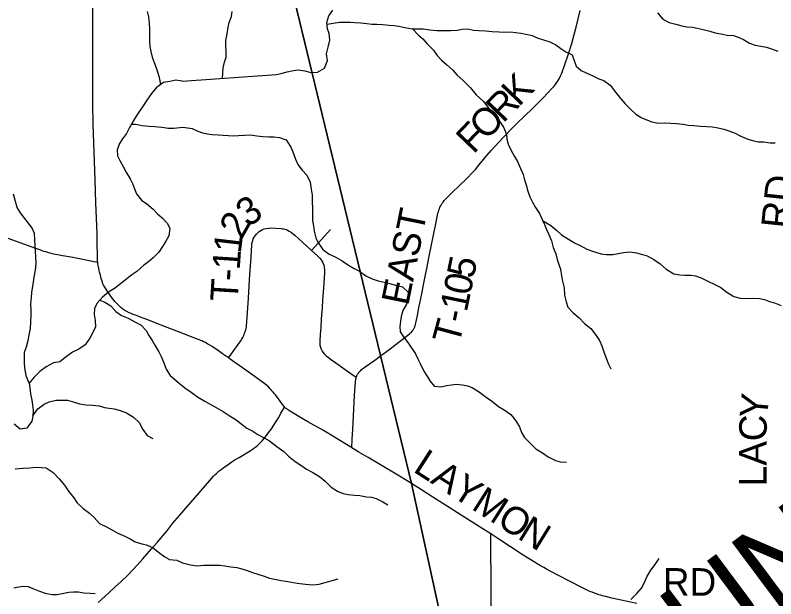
# Model space of a CAD drawing. Extents: x 0 to 48.6, y 0 to 22.
# Drawn here: x 5.524 to 7.09, y 18.416 to 19.616 of the extents above; entities that cross this region are included whole.
import ezdxf

# ---------------------------------------------------------------- set-up
doc = ezdxf.new("R2010")
doc.units = 0
for name, color, linetype in [('GM_X_Corporation', 7, 'Continuous'), ('GM_X_County_Text', 7, 'Continuous'), ('GM_X_Major_River', 7, 'Continuous'), ('GM_X_Minor_River', 7, 'Continuous'), ('GM_X_Township_Road', 7, 'Continuous'), ('GM_X_Township_Road_Text', 7, 'Continuous')]:
    doc.layers.add(name, color=color, linetype=linetype)

msp = doc.modelspace()

# ---------------------------------------------------------------- linework, layer by layer
at = {"layer": 'GM_X_Corporation'}
msp.add_lwpolyline([(5.5264, 17.0064), (5.8387, 17.2541), (6.5365, 17.7727), (6.4996, 17.9212), (6.3396, 18.6531), (6.2759, 18.9159), (6.0412, 19.8859), (5.8236, 20.7829), (5.795, 20.9), (2.1, 20.9), (2.1, 14.1)], dxfattribs=at)
msp.add_lwpolyline([(8.9, 19.5692), (8.9, 20.9), (5.795, 20.9), (5.8236, 20.7829), (6.0412, 19.8859), (6.2759, 18.9159), (6.3396, 18.6531), (6.4996, 17.9212), (6.5365, 17.7727), (6.9471, 18.0777), (7.2261, 18.2847), (8.5348, 19.2897)], close=True, dxfattribs=at)
at = {"layer": 'GM_X_Major_River'}
for points in [[(5.8677, 19.4807), (6.0615, 19.494), (6.071, 19.4961), (6.0835, 19.4998), (6.0965, 19.5026), (6.1067, 19.5036), (6.1203, 19.5019), (6.1328, 19.4987), (6.1461, 19.4993), (6.1606, 19.5071), (6.1665, 19.523), (6.1644, 19.5367), (6.168, 19.5506), (6.1716, 19.565), (6.1699, 19.5783), (6.167, 19.5882), (6.1656, 19.6011), (6.1696, 19.6147), (6.1777, 19.6268)], [(5.8677, 19.4807), (5.8548, 19.4825), (5.8422, 19.4801), (5.8289, 19.4777), (5.8143, 19.467), (5.8045, 19.455), (5.7951, 19.4412), (5.7869, 19.4296), (5.7799, 19.4187), (5.7728, 19.4086), (5.7665, 19.3981), (5.7586, 19.3839), (5.7527, 19.373), (5.7449, 19.3621), (5.7386, 19.3524), (5.7334, 19.3392), (5.7343, 19.3267), (5.739, 19.3171), (5.7467, 19.3033), (5.7529, 19.2921), (5.7606, 19.2795), (5.7654, 19.2699), (5.7693, 19.2592), (5.7733, 19.2489), (5.784, 19.2357), (5.7945, 19.2283), (5.8075, 19.217), (5.8168, 19.2074), (5.8265, 19.1996), (5.8373, 19.188), (5.8424, 19.1773), (5.8398, 19.1621), (5.8339, 19.1516), (5.8268, 19.1404), (5.8197, 19.1288), (5.8077, 19.1172), (5.7981, 19.1091), (5.7884, 19.1021), (5.7745, 19.0887), (5.7641, 19.0821), (5.7533, 19.0739), (5.7437, 19.0665), (5.7305, 19.0554), (5.7159, 19.0466), (5.7036, 19.0362), (5.6915, 19.0228), (5.6871, 19.0127), (5.6865, 19.0005), (5.6885, 18.988), (5.689, 18.975), (5.6842, 18.9645), (5.6771, 18.9518), (5.6681, 18.9383), (5.6547, 18.9291), (5.6416, 18.9233), (5.6285, 18.9137), (5.6158, 18.9033), (5.6028, 18.9009), (5.5875, 18.8925), (5.5748, 18.8832), (5.5631, 18.8717), (5.5526, 18.859), (5.5536, 18.8495), (5.5552, 18.837), (5.558, 18.8244), (5.5597, 18.8149), (5.5606, 18.8035), (5.5599, 18.7909), (5.5578, 18.7807), (5.548, 18.7669), (5.5343, 18.7649), (5.5213, 18.775)]]:
    msp.add_lwpolyline(points, dxfattribs=at)
at = {"layer": 'GM_X_Minor_River'}
for points in [[(5.8236, 19.4738), (5.821, 19.4881), (5.8163, 19.503), (5.8119, 19.5148), (5.8071, 19.527), (5.8035, 19.5415), (5.8017, 19.5518), (5.8007, 19.5613), (5.8012, 19.5719), (5.8007, 19.5882), (5.8001, 19.5993), (5.7987, 19.6126), (5.7962, 19.624)], [(5.9505, 19.4864), (5.9523, 19.5083), (5.9546, 19.5196), (5.9582, 19.5299), (5.9579, 19.542), (5.9572, 19.5526), (5.9573, 19.564), (5.9601, 19.5777), (5.9625, 19.5917), (5.9641, 19.6015), (5.9691, 19.6133), (5.9704, 19.6239)], [(6.8461, 19.6209), (6.8573, 19.6079), (6.8706, 19.6009), (6.8838, 19.5978), (6.8967, 19.5946), (6.9069, 19.5926), (6.9187, 19.5914), (6.9281, 19.5898), (6.9406, 19.587), (6.9543, 19.5835), (6.9652, 19.5803), (6.9766, 19.5779), (6.9895, 19.5755), (7.0028, 19.5743), (7.0126, 19.5712), (7.0235, 19.5661), (7.0356, 19.5588), (7.0477, 19.5545), (7.0705, 19.5505), (7.0811, 19.547), (7.0939, 19.542)], [(6.166, 19.598), (6.1788, 19.6), (6.1918, 19.6018), (6.2039, 19.602), (6.2134, 19.6019), (6.2229, 19.6015), (6.2354, 19.6006), (6.2479, 19.599), (6.2581, 19.5981), (6.2687, 19.5976), (6.2805, 19.5968), (6.2938, 19.5955), (6.304, 19.595), (6.3135, 19.5934), (6.326, 19.591), (6.3411, 19.5883), (6.3514, 19.5882), (6.3639, 19.5884), (6.3772, 19.5864), (6.3916, 19.5851), (6.4022, 19.5847), (6.4208, 19.5845), (6.4341, 19.5855), (6.4443, 19.5873), (6.4557, 19.588), (6.4675, 19.5856), (6.4785, 19.5847), (6.4921, 19.5838), (6.5058, 19.5826), (6.5202, 19.5817), (6.5304, 19.5812), (6.5437, 19.5819), (6.5536, 19.581), (6.5653, 19.579), (6.5786, 19.5766), (6.5884, 19.5742), (6.5986, 19.57), (6.6119, 19.5657), (6.6247, 19.5614), (6.6372, 19.5552), (6.6474, 19.5479), (6.6575, 19.541), (6.6704, 19.5348), (6.6756, 19.5207), (6.6789, 19.5112), (6.6891, 19.5024), (6.6993, 19.4977), (6.7121, 19.4923), (6.7257, 19.4853), (6.7356, 19.4818), (6.7488, 19.4726), (6.7596, 19.4581), (6.7709, 19.4439), (6.7799, 19.434), (6.7916, 19.4221), (6.8014, 19.4129), (6.8127, 19.4056), (6.8225, 19.4017), (6.8346, 19.397), (6.8482, 19.3943), (6.8604, 19.3949), (6.8737, 19.394), (6.8854, 19.3935), (6.8991, 19.3919), (6.9097, 19.3903), (6.9214, 19.3894), (6.9351, 19.3882), (6.9476, 19.3873), (6.9586, 19.3868), (6.9681, 19.3852), (6.9828, 19.3817), (6.993, 19.3781), (7.0063, 19.3735), (7.018, 19.3677), (7.0324, 19.3611), (7.0445, 19.3576), (7.0543, 19.356), (7.0646, 19.3555), (7.0782, 19.3535), (7.0884, 19.3538)], [(6.3419, 19.5882), (6.3532, 19.5756), (6.3633, 19.5676), (6.372, 19.5572), (6.3848, 19.5446), (6.3926, 19.5335), (6.4017, 19.5239), (6.4126, 19.5144), (6.4239, 19.5036), (6.4329, 19.4937), (6.4464, 19.4818), (6.4611, 19.4665), (6.4731, 19.4527), (6.487, 19.4393), (6.4979, 19.4263), (6.5084, 19.414), (6.5193, 19.4003), (6.5294, 19.3861), (6.5354, 19.3717), (6.5361, 19.361), (6.539, 19.3511), (6.5453, 19.3378), (6.5521, 19.3256), (6.5577, 19.3153), (6.564, 19.3012), (6.5696, 19.2886), (6.5725, 19.2776), (6.5758, 19.2673), (6.5791, 19.254), (6.5836, 19.2426), (6.5892, 19.2319), (6.5951, 19.2204), (6.603, 19.2082), (6.6086, 19.196), (6.6138, 19.1854), (6.6179, 19.1754), (6.6227, 19.1648), (6.6283, 19.1522), (6.6316, 19.1381), (6.6368, 19.1252), (6.6394, 19.1138), (6.6431, 19.1035), (6.6464, 19.0936), (6.6489, 19.0803), (6.6507, 19.0693), (6.654, 19.0556), (6.6546, 19.04), (6.6583, 19.0267), (6.662, 19.0153), (6.6729, 19.0038), (6.6842, 18.9946), (6.6963, 18.9823), (6.7087, 18.9719), (6.7203, 18.957), (6.7267, 18.9467), (6.7315, 18.9361), (6.7356, 18.9235), (6.7404, 18.9105), (6.7456, 18.8983), (6.7504, 18.8888)], [(5.7631, 19.392), (5.7715, 19.392), (5.7852, 19.3895), (5.7988, 19.3878), (5.8113, 19.3873), (5.8254, 19.386), (5.8394, 19.3835), (5.8502, 19.3837), (5.8688, 19.3857)], [(5.8688, 19.3857), (5.8878, 19.3832), (5.8995, 19.3778), (5.9094, 19.3743), (5.9196, 19.3719), (5.929, 19.3707), (5.9419, 19.3702), (5.9518, 19.3697), (5.9632, 19.3689), (5.9742, 19.3684), (5.9837, 19.3687), (5.9962, 19.3697), (6.0091, 19.37), (6.0216, 19.3684), (6.0334, 19.3667), (6.0459, 19.3662), (6.0561, 19.3661), (6.0682, 19.3645), (6.0819, 19.3598), (6.0912, 19.3449), (6.0953, 19.335), (6.1009, 19.3202), (6.1057, 19.3088), (6.1147, 19.2973), (6.1241, 19.2873), (6.1308, 19.2729), (6.1333, 19.2584), (6.1351, 19.2459), (6.1354, 19.233), (6.1356, 19.2185), (6.1359, 19.206), (6.1362, 19.1935), (6.138, 19.1832), (6.1394, 19.1718), (6.1427, 19.1585), (6.1468, 19.149), (6.1569, 19.1345), (6.1701, 19.1249), (6.1826, 19.119), (6.1973, 19.1109), (6.2101, 19.1021), (6.2218, 19.0948), (6.2324, 19.0894), (6.2456, 19.0801), (6.2588, 19.0739), (6.2709, 19.07), (6.2808, 19.0677), (6.2948, 19.0641), (6.3065, 19.061), (6.3213, 19.0571), (6.3329, 19.0463), (6.3351, 19.0364), (6.3293, 19.0217), (6.322, 19.0085), (6.3188, 18.9964), (6.3172, 18.9865), (6.316, 18.9755), (6.3167, 18.9649), (6.3234, 18.9546), (6.3324, 18.9427), (6.3388, 18.9328), (6.3474, 18.9206), (6.353, 18.9095), (6.3578, 18.8996), (6.3649, 18.884), (6.3716, 18.874), (6.3784, 18.863), (6.3866, 18.853), (6.401, 18.8517), (6.4117, 18.8543), (6.4219, 18.8561), (6.4318, 18.8572), (6.4447, 18.8555), (6.4549, 18.8539), (6.4648, 18.85), (6.4795, 18.8408), (6.4938, 18.8304), (6.5047, 18.8227), (6.5187, 18.8112), (6.5308, 18.8043), (6.5443, 18.795), (6.5549, 18.782), (6.5623, 18.7691), (6.566, 18.7576), (6.5724, 18.7477), (6.5844, 18.7358), (6.5961, 18.7243), (6.6097, 18.7159), (6.6213, 18.7074), (6.6361, 18.7004), (6.6459, 18.6977), (6.6588, 18.6968)], [(5.5526, 18.859), (5.5467, 18.8725), (5.5446, 18.8862), (5.5432, 18.8992), (5.543, 18.9094), (5.5432, 18.9227), (5.5467, 18.9337), (5.5503, 18.9469), (5.5527, 18.9583), (5.5552, 18.9715), (5.5561, 18.9852), (5.5567, 18.9988), (5.5564, 19.0095), (5.5562, 19.0216), (5.5572, 19.0353), (5.5581, 19.0455), (5.5606, 19.0626), (5.563, 19.0773), (5.5655, 19.0917), (5.5668, 19.105), (5.5663, 19.1198), (5.5656, 19.1297), (5.565, 19.1411), (5.5644, 19.1551), (5.5638, 19.1669), (5.559, 19.1784), (5.5508, 19.1883), (5.5437, 19.1983), (5.5348, 19.2098), (5.5281, 19.2209), (5.5241, 19.2327), (5.5205, 19.2479)], [(6.6098, 19.1936), (6.6267, 19.1833), (6.6387, 19.173), (6.6489, 19.1645), (6.6629, 19.1557), (6.6753, 19.148), (6.6874, 19.1426), (6.701, 19.1348), (6.7146, 19.1302), (6.7301, 19.1251), (6.7411, 19.1239), (6.7544, 19.1241), (6.7651, 19.1263), (6.7765, 19.1281), (6.7898, 19.1291), (6.8034, 19.1271), (6.8155, 19.1239), (6.8253, 19.1212), (6.8389, 19.1139), (6.8518, 19.1046), (6.8642, 19.0935), (6.8797, 19.0843), (6.8925, 19.0822), (6.9028, 19.0814), (6.9153, 19.0817), (6.9248, 19.0801), (6.9373, 19.075), (6.9497, 19.0688), (6.9645, 19.0622), (6.9765, 19.0557), (6.9894, 19.0461), (7.0037, 19.0372), (7.0166, 19.0341), (7.0272, 19.0336), (7.042, 19.0338), (7.056, 19.0333), (7.0666, 19.0313), (7.0772, 19.0274), (7.0871, 19.0243), (7.101, 19.0192)], [(5.6979, 19.0299), (5.7082, 19.0257), (5.721, 19.0183), (5.7311, 19.0064), (5.7428, 18.9987), (5.7564, 18.9928), (5.77, 18.9854), (5.7832, 18.9784), (5.7933, 18.9677), (5.7992, 18.957), (5.8059, 18.947), (5.8111, 18.9371), (5.8193, 18.9237), (5.8241, 18.9141), (5.8296, 18.9011), (5.8348, 18.8878), (5.843, 18.8752), (5.8617, 18.8589)], [(5.8617, 18.8589), (5.8732, 18.8493), (5.8861, 18.8409), (5.8993, 18.8312), (5.914, 18.8224), (5.9238, 18.8166), (5.9378, 18.8089), (5.9517, 18.8008), (5.9642, 18.7927), (5.9785, 18.7838), (5.9883, 18.7765), (6.0004, 18.7669), (6.0128, 18.7604), (6.0234, 18.7538), (6.0362, 18.7465), (6.0472, 18.7403), (6.0623, 18.7288), (6.0766, 18.7184), (6.0864, 18.7092), (6.1003, 18.6981), (6.1139, 18.6889), (6.1237, 18.6823), (6.1369, 18.6754), (6.1501, 18.6669), (6.1622, 18.6573), (6.1742, 18.6454), (6.1874, 18.637), (6.1991, 18.6323), (6.2094, 18.6299), (6.2222, 18.6287), (6.2336, 18.6278), (6.2469, 18.6254), (6.2571, 18.6246), (6.2673, 18.6218), (6.2806, 18.6152), (6.2907, 18.6087)], [(5.56, 18.7922), (5.5701, 18.8062), (5.5831, 18.8163), (5.5935, 18.8207), (5.6079, 18.8239), (5.6209, 18.8245), (5.6315, 18.824), (5.6413, 18.8216), (5.6561, 18.8168), (5.6697, 18.8144), (5.683, 18.8142), (5.6963, 18.8129), (5.7073, 18.8093), (5.7171, 18.8077), (5.7273, 18.8064), (5.7402, 18.8032), (5.7531, 18.7985), (5.7674, 18.7896), (5.779, 18.778), (5.7868, 18.7639), (5.7957, 18.7513), (5.8071, 18.7454)], [(5.5237, 18.683), (5.54, 18.6843), (5.5529, 18.6849), (5.567, 18.6863), (5.578, 18.6857), (5.5875, 18.6849), (5.6022, 18.6752), (5.6142, 18.6621), (5.625, 18.6495), (5.6332, 18.6368), (5.6444, 18.6234), (5.6507, 18.6138), (5.6639, 18.6015), (5.6767, 18.5918), (5.6864, 18.583), (5.6976, 18.5703), (5.712, 18.5633), (5.7256, 18.5563), (5.7354, 18.5508), (5.7493, 18.5446), (5.7607, 18.5387), (5.7708, 18.5329), (5.7844, 18.5289), (5.7943, 18.5265), (5.8079, 18.5203), (5.8188, 18.5114), (5.8316, 18.5021), (5.8414, 18.4967), (5.8567, 18.495)], [(6.8194, 18.449), (6.8244, 18.4608), (6.8325, 18.4747), (6.8417, 18.486), (6.8498, 18.4985)], [(5.8567, 18.495), (5.8685, 18.4899), (5.8844, 18.4856), (5.8981, 18.4836), (5.9121, 18.4846), (5.9242, 18.4845), (5.9349, 18.4848), (5.9451, 18.485), (5.9557, 18.4834), (5.9679, 18.4814), (5.9804, 18.4798), (5.9902, 18.477), (6.0016, 18.4739), (6.0125, 18.4696), (6.0235, 18.4661), (6.0364, 18.4622), (6.0473, 18.4583), (6.0613, 18.4551), (6.0712, 18.4532), (6.0894, 18.4507), (6.1045, 18.4479), (6.1212, 18.4455), (6.1364, 18.4446), (6.1497, 18.4456), (6.1618, 18.4489), (6.1763, 18.453), (6.1888, 18.4566)], [(6.7914, 18.4144), (6.804, 18.4268), (6.8132, 18.4373), (6.8194, 18.449)], [(5.5208, 18.4378), (5.5314, 18.44), (5.541, 18.4417), (5.5504, 18.4412), (5.5603, 18.4366), (5.5735, 18.4315), (5.5856, 18.4271), (5.6, 18.4247), (5.6099, 18.4245), (5.6239, 18.427), (5.6342, 18.4291), (5.6441, 18.4298), (5.6536, 18.4297), (5.6654, 18.4276), (5.6783, 18.4271), (5.6881, 18.4262)]]:
    msp.add_lwpolyline(points, dxfattribs=at)
at = {"layer": 'GM_X_Township_Road'}
for points in [[(5.6936, 19.1083), (5.6935, 19.109), (5.6933, 19.1126), (5.693, 19.1281), (5.6928, 19.1405), (5.6922, 19.1672), (5.6898, 19.2305), (5.6881, 19.2777), (5.6845, 19.3913), (5.6835, 19.4336), (5.6833, 19.492), (5.6835, 19.5298), (5.6833, 19.5752), (5.6837, 19.6336)], [(6.2761, 18.9154), (6.2858, 18.9223), (6.2957, 18.9297), (6.3085, 18.9395), (6.3321, 18.9577), (6.3364, 18.9613), (6.3379, 18.9628), (6.3395, 18.9643), (6.3409, 18.966), (6.3423, 18.9677), (6.3435, 18.9697), (6.3446, 18.9713), (6.3456, 18.9734), (6.3464, 18.9753), (6.3472, 18.9775), (6.348, 18.98), (6.3488, 18.9831), (6.3495, 18.986), (6.3518, 18.9982), (6.355, 19.014), (6.3608, 19.0427), (6.3653, 19.0652), (6.3686, 19.0823), (6.3719, 19.0987), (6.3754, 19.117), (6.38, 19.1402), (6.3896, 19.187), (6.3926, 19.2017), (6.3943, 19.2089), (6.3951, 19.2117), (6.396, 19.2149), (6.3972, 19.2182), (6.3984, 19.2213), (6.3999, 19.2242), (6.4013, 19.2268), (6.4031, 19.2293), (6.4048, 19.2319), (6.407, 19.2347), (6.4093, 19.237), (6.4158, 19.2437), (6.4242, 19.252), (6.437, 19.2647), (6.4536, 19.2806), (6.4654, 19.2925), (6.4713, 19.2989), (6.4786, 19.3074), (6.4952, 19.3274), (6.5041, 19.3378), (6.5202, 19.3558), (6.5297, 19.3657), (6.5492, 19.3857), (6.5575, 19.3941), (6.5883, 19.4239), (6.6106, 19.4463), (6.6206, 19.4565), (6.6296, 19.466), (6.6326, 19.4695), (6.6361, 19.4735), (6.6385, 19.4769), (6.6407, 19.4801), (6.6427, 19.4835), (6.6444, 19.4866), (6.6457, 19.4893), (6.6468, 19.4916), (6.6483, 19.4954), (6.6498, 19.4991), (6.6547, 19.5125), (6.6622, 19.5349), (6.6696, 19.558), (6.674, 19.5735), (6.6788, 19.5916), (6.6871, 19.626)], [(5.9628, 18.9111), (5.9682, 18.9186), (5.9882, 18.9463), (5.9899, 18.9491), (5.9911, 18.951), (5.9922, 18.953), (5.9931, 18.9548), (5.9942, 18.9572), (5.9954, 18.9598), (5.9964, 18.9627), (5.9975, 18.9656), (5.9983, 18.9687), (5.9991, 18.9715), (5.9997, 18.9745), (6.0002, 18.9775), (6.001, 18.9855), (6.004, 19.0344), (6.0062, 19.0717), (6.0075, 19.0915), (6.0093, 19.1182), (6.0102, 19.1324), (6.0109, 19.1424), (6.0113, 19.1454), (6.0118, 19.1486), (6.0129, 19.1529), (6.014, 19.1559), (6.0157, 19.1593), (6.0178, 19.1626), (6.0206, 19.1661), (6.0233, 19.1688), (6.0262, 19.1712), (6.0294, 19.1734), (6.0328, 19.1752), (6.0363, 19.1766), (6.0406, 19.1777), (6.045, 19.1784), (6.0507, 19.1785), (6.0595, 19.1781), (6.0713, 19.1773), (6.0743, 19.1768), (6.0769, 19.1765), (6.0794, 19.1758), (6.0818, 19.1751), (6.0847, 19.1739), (6.0881, 19.1721), (6.0929, 19.1689), (6.1, 19.1628), (6.1154, 19.1492), (6.1337, 19.1322)], [(6.1337, 19.1322), (6.1478, 19.1473), (6.167, 19.1686), (6.173, 19.1751)], [(5.5089, 19.1577), (5.5654, 19.1368), (5.5755, 19.1333), (5.5788, 19.1321), (5.5823, 19.1311), (5.5864, 19.1299), (5.5901, 19.1288), (5.5925, 19.1282), (5.5973, 19.127), (5.6027, 19.1256), (5.6067, 19.1247), (5.6106, 19.1238), (5.6143, 19.1231), (5.6208, 19.1219), (5.6258, 19.1209), (5.6423, 19.1183), (5.6895, 19.1091), (5.6936, 19.1083)], [(6.1337, 19.1322), (6.1469, 19.1207), (6.1489, 19.1187), (6.1508, 19.1167), (6.1536, 19.1132), (6.1547, 19.1115), (6.156, 19.1094), (6.1571, 19.1072), (6.1579, 19.1054), (6.1592, 19.1018), (6.16, 19.0987), (6.1602, 19.0962), (6.1606, 19.0931), (6.1606, 19.0898), (6.1605, 19.0861), (6.1584, 19.0545), (6.1567, 19.031), (6.1556, 19.0143), (6.1539, 18.9914), (6.1528, 18.9734), (6.1516, 18.9592), (6.1509, 18.9462), (6.1509, 18.9419), (6.1513, 18.9377), (6.1523, 18.933), (6.1538, 18.929), (6.1557, 18.9253), (6.1573, 18.9227), (6.1599, 18.9194), (6.1643, 18.9152), (6.1687, 18.9118), (6.1747, 18.9074), (6.1838, 18.901), (6.2127, 18.8806), (6.2214, 18.8746), (6.2261, 18.8714)], [(5.9628, 18.9111), (5.9507, 18.9197), (5.9395, 18.9276), (5.934, 18.9313), (5.9292, 18.9345), (5.9248, 18.9372), (5.9207, 18.9397), (5.9181, 18.9411), (5.9153, 18.9426), (5.9116, 18.9443), (5.908, 18.946), (5.8971, 18.9505), (5.86, 18.9645), (5.8155, 18.9822), (5.797, 18.9895), (5.7871, 18.9931), (5.7784, 18.9963), (5.7714, 18.9989), (5.7667, 19.0006), (5.7626, 19.0024), (5.7587, 19.004), (5.7537, 19.0065), (5.7483, 19.0097), (5.7447, 19.0122), (5.7414, 19.0149), (5.7384, 19.0177), (5.7351, 19.0208), (5.7297, 19.0268), (5.72, 19.039), (5.7142, 19.0471), (5.7095, 19.0544), (5.7082, 19.0565), (5.7071, 19.0585), (5.7057, 19.0609), (5.7045, 19.0637), (5.7038, 19.0657), (5.7034, 19.067), (5.701, 19.0743), (5.6991, 19.0815), (5.6975, 19.0877), (5.6966, 19.0917), (5.6958, 19.0948), (5.6951, 19.0984), (5.6945, 19.1014), (5.6941, 19.1039), (5.6938, 19.1066), (5.6936, 19.1083)], [(6.0783, 18.8104), (6.0767, 18.8121), (6.0754, 18.8137), (6.0742, 18.8151), (6.0725, 18.8175), (6.0657, 18.8271), (6.0623, 18.8318), (6.0599, 18.8349), (6.0577, 18.8375), (6.0547, 18.8409), (6.0524, 18.8436), (6.0501, 18.8463), (6.048, 18.8485), (6.0458, 18.851), (6.0376, 18.8576), (6.0132, 18.8758), (5.9985, 18.8862), (5.9709, 18.9053), (5.9628, 18.9111)], [(6.2261, 18.8714), (6.2264, 18.8722), (6.2269, 18.8738), (6.2275, 18.8753), (6.2281, 18.8767), (6.2289, 18.878), (6.2297, 18.8793), (6.2306, 18.8805), (6.2316, 18.8818), (6.2325, 18.8828), (6.2337, 18.8841), (6.2352, 18.8855), (6.237, 18.887), (6.2444, 18.8926), (6.2641, 18.9066), (6.2761, 18.9154)], [(6.2169, 18.7262), (6.2178, 18.7438), (6.2189, 18.7649), (6.2202, 18.791), (6.2227, 18.8344), (6.2244, 18.8611), (6.2247, 18.8634), (6.225, 18.866), (6.2254, 18.8683), (6.2258, 18.8703), (6.2261, 18.8714)], [(5.6949, 18.4079), (5.7162, 18.4278), (5.7292, 18.4394), (5.742, 18.4512), (5.7559, 18.4643), (5.7756, 18.4857), (5.7864, 18.4976), (5.7955, 18.5078), (5.8044, 18.5181), (5.8158, 18.5313), (5.8357, 18.555), (5.8485, 18.5709), (5.885, 18.6133), (5.9244, 18.6589), (5.9322, 18.6677), (5.9356, 18.6714), (5.9382, 18.6737), (5.9412, 18.6764), (5.944, 18.6787), (5.9481, 18.6819), (5.9516, 18.6844), (5.9602, 18.6906), (5.9745, 18.7005), (5.9808, 18.7045), (5.9846, 18.7066), (6.004, 18.7176), (6.0075, 18.7198), (6.0118, 18.7225), (6.0154, 18.7252), (6.0192, 18.7281), (6.0219, 18.7305), (6.0256, 18.7338), (6.029, 18.7373), (6.0324, 18.7409), (6.0354, 18.7444), (6.038, 18.7476), (6.0411, 18.7515), (6.0441, 18.7554), (6.0513, 18.7654), (6.06, 18.7782), (6.0627, 18.7827), (6.0657, 18.7877), (6.0684, 18.7926), (6.071, 18.7973), (6.0741, 18.8029), (6.0783, 18.8104)], [(6.2169, 18.7262), (6.2147, 18.7275), (6.1815, 18.7482), (6.1584, 18.7617), (6.1266, 18.7799), (6.1061, 18.7915), (6.0923, 18.7999), (6.0884, 18.8023), (6.0868, 18.8034), (6.085, 18.8047), (6.0826, 18.8064), (6.0818, 18.8071), (6.0806, 18.8081), (6.0783, 18.8104)], [(6.3399, 18.6526), (6.3151, 18.6679), (6.2693, 18.6954), (6.2505, 18.7064), (6.2312, 18.7175), (6.2169, 18.7262)], [(6.5032, 18.5489), (6.4758, 18.5663), (6.4344, 18.5926), (6.4175, 18.6031), (6.3839, 18.6244), (6.3605, 18.6397), (6.3399, 18.6526)], [(6.4999, 17.9207), (6.5002, 17.9274), (6.503, 17.997), (6.5043, 18.0274), (6.5051, 18.0521), (6.5059, 18.0645), (6.5064, 18.0744), (6.507, 18.0906), (6.5077, 18.1129), (6.5077, 18.1199), (6.5077, 18.1421), (6.5071, 18.1893), (6.5067, 18.2409), (6.5063, 18.2732), (6.506, 18.2949), (6.5051, 18.3409), (6.5048, 18.367), (6.5038, 18.4347), (6.5035, 18.4639), (6.503, 18.5086), (6.5031, 18.5229), (6.5032, 18.5391), (6.5032, 18.5489)], [(6.8038, 18.4058), (6.7522, 18.4171), (6.7396, 18.4202), (6.7359, 18.4211), (6.733, 18.4219), (6.7298, 18.4228), (6.7257, 18.424), (6.7204, 18.4258), (6.7163, 18.4271), (6.7117, 18.4289), (6.709, 18.4301), (6.7059, 18.4314), (6.6919, 18.438), (6.6625, 18.4529), (6.6268, 18.4716), (6.6176, 18.4767), (6.6121, 18.4797), (6.6053, 18.4837), (6.5986, 18.4875), (6.5943, 18.4902), (6.5699, 18.5054), (6.5176, 18.5394), (6.5073, 18.5463), (6.5032, 18.5489)]]:
    msp.add_lwpolyline(points, dxfattribs=at)

# ---------------------------------------------------------------- texts
at = {"layer": 'GM_X_County_Text'}
for s, rotation, p in [('HIGHLAND COUNTY', 37.2438, (6.9412, 17.5789)), ('CLINTON COUNTY', 36.7754, (5.6985, 17.3231))]:
    msp.add_text(s, height=0.189394, rotation=rotation, dxfattribs=at).set_placement(p)
at = {"layer": 'GM_X_Township_Road_Text'}
for s, height, rotation, p in [('K', 0.0568, 46.2231, (6.5608, 19.4265)), ('R', 0.0568, 46.1409, (6.5285, 19.3928)), ('O', 0.0568, 46.1385, (6.4938, 19.3568)), ('F', 0.0568, 46.1424, (6.4672, 19.3291)), ('RD', 0.05682, 84.0908, (7.116, 19.1757)), ('3', 0.0568, 33.6029, (6.0027, 19.1789)), ('EAST', 0.05682, 78.4756, (6.3329, 19.0171)), ('2', 0.0568, 60.608, (5.9904, 19.1538)), ('1', 0.0568, 83.3309, (5.9882, 19.1249)), ('1', 0.0568, 86.2106, (5.986, 19.091)), ('5', 0.0568, 78.5148, (6.4675, 19.0725)), ('-', 0.0568, 86.3294, (5.9845, 19.068)), ('0', 0.0568, 78.4967, (6.4606, 19.0381)), ('T', 0.0568, 86.3814, (5.9818, 19.0257)), ('1', 0.0568, 78.4635, (6.4536, 19.0038)), ('-', 0.0568, 78.4946, (6.4489, 18.981)), ('T', 0.0568, 74.9565, (6.437, 18.9362)), ('Y', 0.0568, 84.6044, (7.0717, 18.7847)), ('C', 0.0568, 88.9188, (7.0708, 18.7392)), ('A', 0.0568, 89.9927, (7.0708, 18.6895)), ('L', 0.0568, 327.375, (6.341, 18.6784)), ('A', 0.0568, 327.3787, (6.3768, 18.6554)), ('L', 0.0568, 90, (7.0708, 18.647)), ('Y', 0.0568, 327.3749, (6.4189, 18.6285)), ('M', 0.0568, 327.3789, (6.461, 18.6015)), ('O', 0.0568, 327.3981, (6.513, 18.5683)), ('N', 0.0568, 328.2727, (6.5559, 18.5408)), ('RD', 0.05682, 0, (6.8574, 18.4218))]:
    msp.add_text(s, height=height, rotation=rotation, dxfattribs=at).set_placement(p)

doc.saveas('drawing.dxf')
